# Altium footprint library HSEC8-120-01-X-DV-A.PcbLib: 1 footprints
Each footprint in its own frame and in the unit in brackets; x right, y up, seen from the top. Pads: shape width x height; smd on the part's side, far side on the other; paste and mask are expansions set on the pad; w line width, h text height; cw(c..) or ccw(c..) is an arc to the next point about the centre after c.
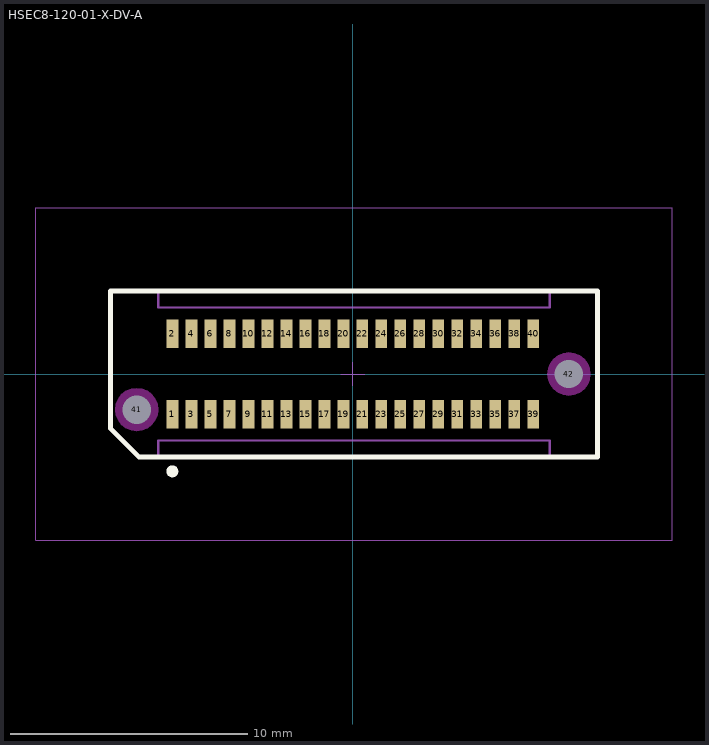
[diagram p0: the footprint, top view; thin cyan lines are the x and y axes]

## HSEC8-120-01-X-DV-A [mm] "0.80mm pitch, 40 pin, hi-speed micro edge card; w/alignment pins"
height 7.98
pads (42):
  rect 0.5x1.2 smd mask+0: 1(-7.6,-1.7) 2(-7.6,1.7) 3(-6.8,-1.7) 4(-6.8,1.7) 5(-6,-1.7) 6(-6,1.7) 7(-5.2,-1.7) 8(-5.2,1.7) 9(-4.4,-1.7) 10(-4.4,1.7) 11(-3.6,-1.7) 12(-3.6,1.7) 13(-2.8,-1.7) 14(-2.8,1.7) 15(-2,-1.7) 16(-2,1.7) 17(-1.2,-1.7) 18(-1.2,1.7) 19(-0.4,-1.7) 20(-0.4,1.7) 21(0.4,-1.7) 22(0.4,1.7) 23(1.2,-1.7) 24(1.2,1.7) 25(2,-1.7) 26(2,1.7) 27(2.8,-1.7) 28(2.8,1.7) 29(3.6,-1.7) 30(3.6,1.7) 31(4.4,-1.7) 32(4.4,1.7) 33(5.2,-1.7) 34(5.2,1.7) 35(6,-1.7) 36(6,1.7) 37(6.8,-1.7) 38(6.8,1.7) 39(7.6,-1.7) 40(7.6,1.7)
  round 0.5 hole 1.2 unplated mask+0: 41(-9.1,-1.5) 42(9.1,0)
Top Overlay:
  circle w0.25: c-7.6,-4.1 r0.125
  lines w0.2: -10.2,-2.3 -10.2,3.5 10.3,3.5 10.3,-3.5 -9,-3.5 -10.2,-2.3
Keep-Out Layer:
  pour cut-out: 10.008,0 9.977,0.235 9.886,0.454 9.742,0.642 9.554,0.786 9.335,0.877 9.1,0.908 8.865,0.877 8.646,0.786 8.458,0.642 8.314,0.454 8.223,0.235 8.192,0 8.223,-0.235 8.314,-0.454 8.458,-0.642 8.646,-0.786 8.865,-0.877 9.1,-0.908 9.335,-0.877 9.554,-0.786 9.742,-0.642 9.886,-0.454 9.977,-0.235
  pour cut-out: -8.192,-1.5 -8.223,-1.265 -8.314,-1.046 -8.458,-0.858 -8.646,-0.714 -8.865,-0.623 -9.1,-0.592 -9.335,-0.623 -9.554,-0.714 -9.742,-0.858 -9.886,-1.046 -9.977,-1.265 -10.008,-1.5 -9.977,-1.735 -9.886,-1.954 -9.742,-2.142 -9.554,-2.286 -9.335,-2.377 -9.1,-2.408 -8.865,-2.377 -8.646,-2.286 -8.458,-2.142 -8.314,-1.954 -8.223,-1.735
Mechanical 12:
  lines w0.001: -10.2,-2.3 -10.2,3.5 10.3,3.5 10.3,-3.5 -9,-3.5 -10.2,-2.3
Mechanical 13:
  lines w0.1: -10.2,-2.3 -10.2,2.794 -10.2,3.5 -8.199,3.5 -8.199,2.8 8.3,2.8 8.3,3.5 10.3,3.5 10.3,-3.5 8.3,-3.5 8.3,-2.8 -8.2,-2.8 -8.2,-3.5 -9,-3.5 -10.2,-2.3
  text ".Designator" at 0.254,0.254 h1.52
Mechanical 15:
  lines w0.05: -0.5,0 0.5,0 ; 0,-0.5 0,0.5 ; -13.35,-7 -13.35,7 13.45,7 13.45,-7 -13.35,-7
